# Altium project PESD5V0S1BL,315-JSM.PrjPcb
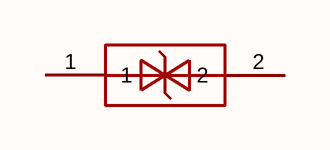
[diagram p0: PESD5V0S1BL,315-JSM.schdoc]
1 sheet, 1 parts. Net scope: global (net labels, ports and power ports of the same name join across sheets).

## Sheet PESD5V0S1BL,315-JSM.schdoc
size 127 x 101 mm

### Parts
D?  pesd5v0s1bl,315-jsm  [DFN1006-2L-BI]  (value not drawn)

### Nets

Not connected (* = marked no-connect by the designer): D? 1 2

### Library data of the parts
D? = pesd5v0s1bl,315-jsm: 极性:-;反向截止电压(Vrwm):5V;钳位电压:17V;峰值脉冲电流(Ipp):5A@8/20us;峰值脉冲功率(Ppp):68W@8/20us;击穿电压(VBR):9V;; Manufacturer: JSMSEMI(杰盛微); AddInBom: yes; ModelId: 2bdbcca3b35b49c5a8ae725a08658930; ModelTransform: 40.1574,24.4094,0,0,0,0,0,0,0; Reverse Stand-Off Voltage (Vrwm): 5V; Clamping Voltage: 17V; Voltage - Breakdown: 9V; Reverse Leakage Current (Ir): 100nA; Number of Channels: 单路; level of protection: IEC 61000-4-2; Type: ESD; Junction Capacitance: 8.9pF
